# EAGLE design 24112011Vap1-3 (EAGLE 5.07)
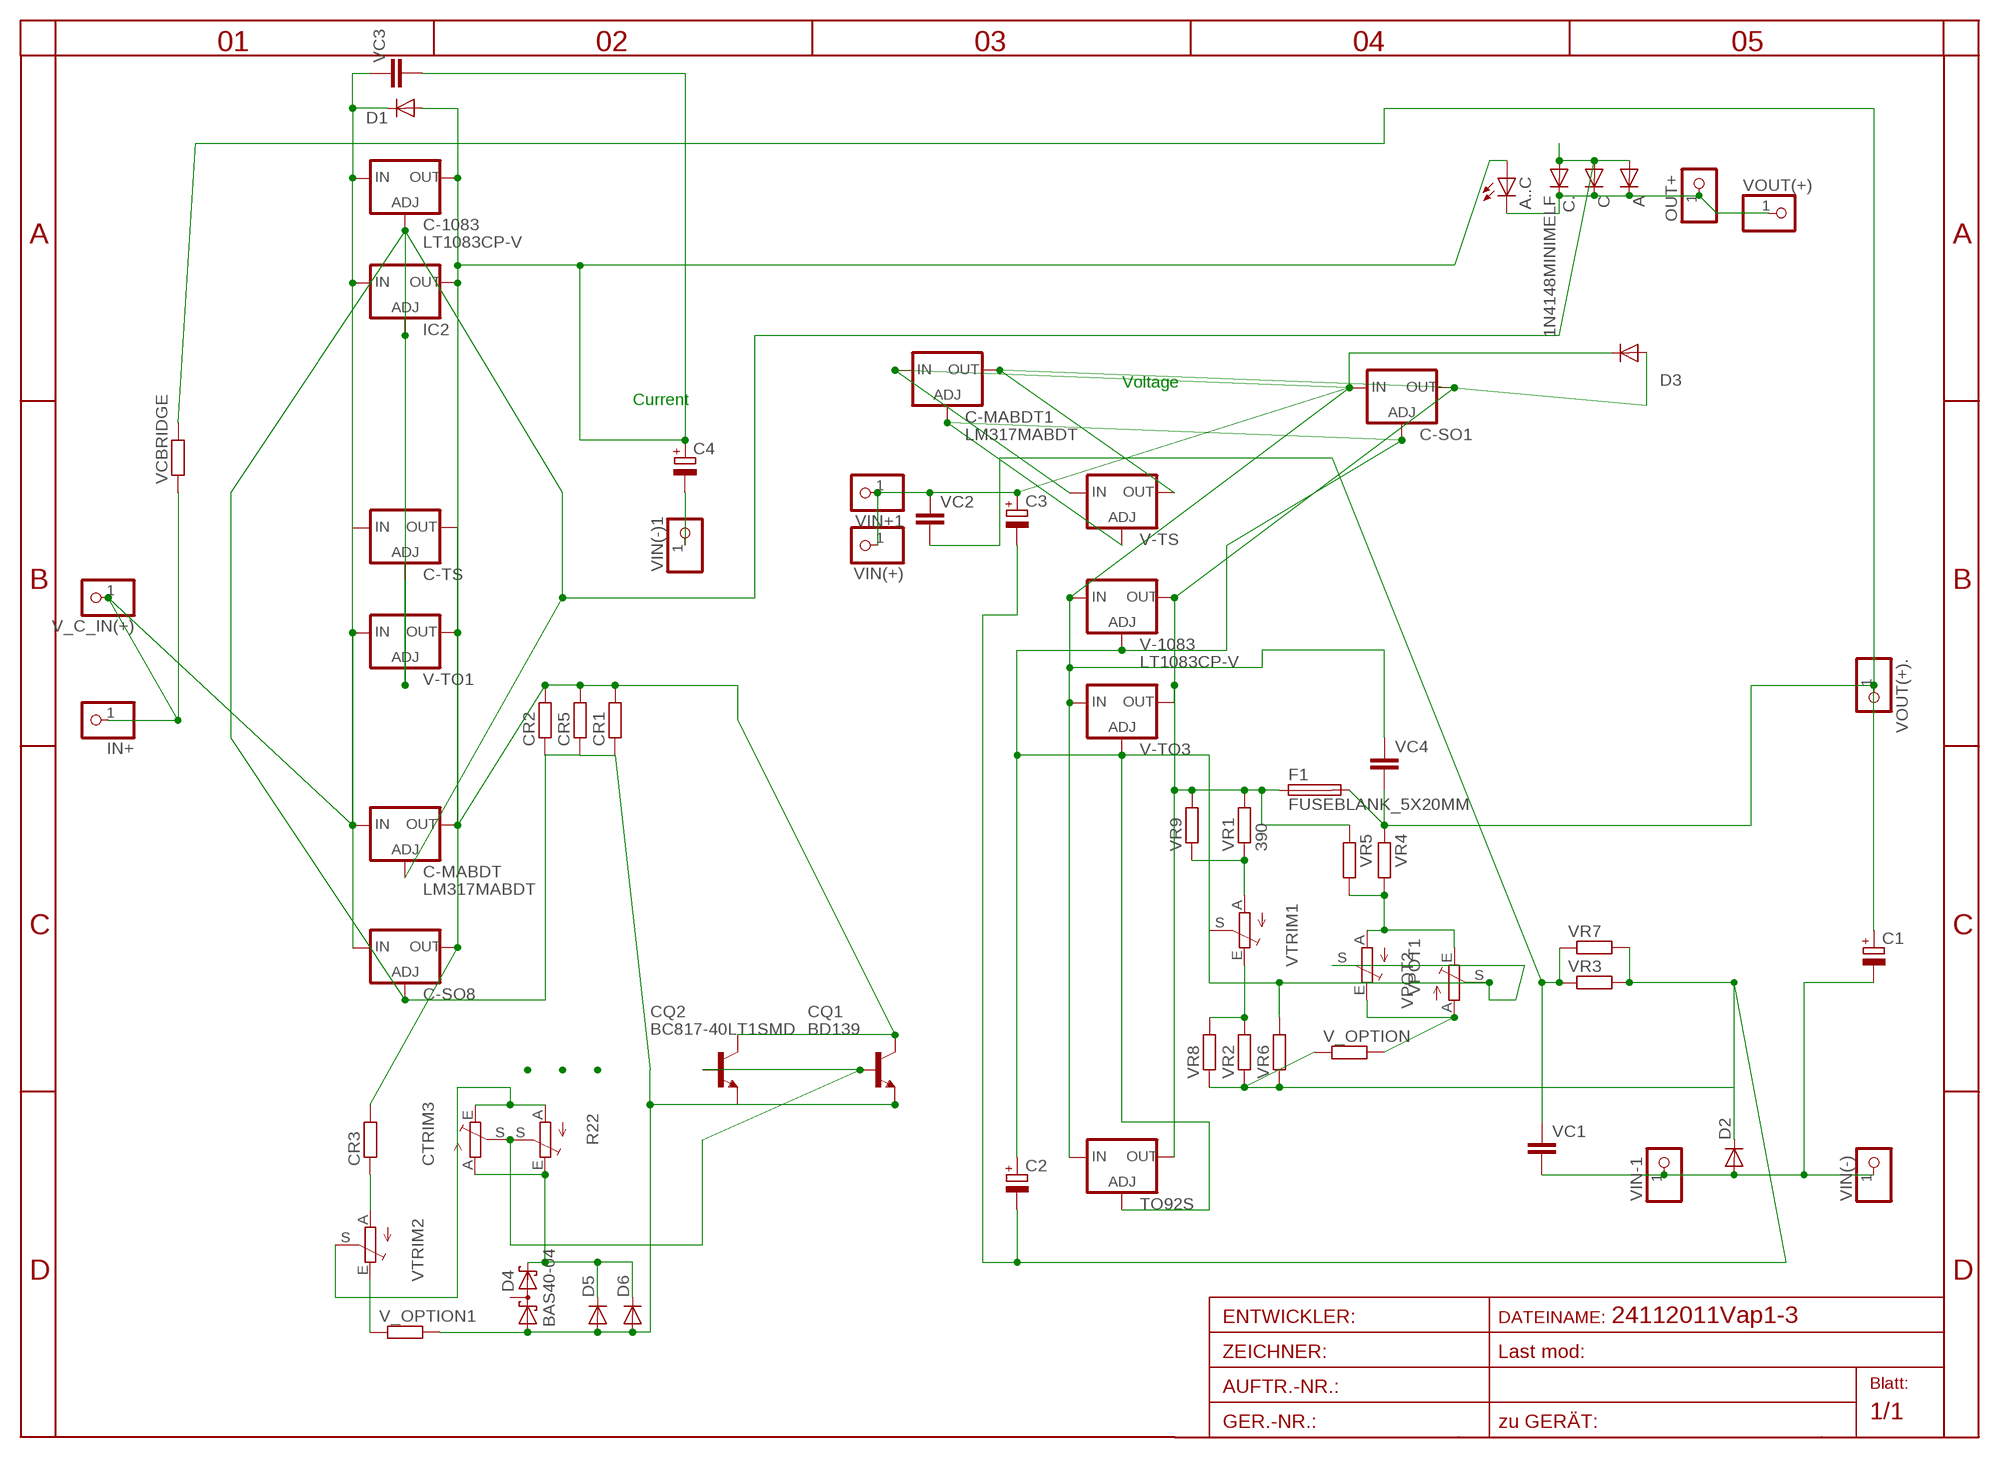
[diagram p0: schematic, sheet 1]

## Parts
A  DIODE-TO220V  [TO220ACS]
A..C  LED3MM  [LED3MM]
C  DIODE-SMC  [SMC]
C1  CPOL-EUE5-8.5  [E5-8,5]
C2  CPOL-EUE2.5-6  [E2,5-6]
C3  CPOL-EUE2.5-6  [E2,5-6]
C4  CPOL-EUE5-6  [E5-6]
C-1083  LT1083CP-V  [TO247S]
C-MABDT  LM317MABDT  [DPACK]
C-MABDT1  LM317MABDT  [DPACK]
C-SO1  LM317LM-OUTPIN7  [SO08]
C-SO8  LM317LM-OUTPIN7  [SO08]
C-TS  LM317TS  [317TS]
C.  1N4148MINIMELF  [MINIMELF]
CQ1  BD139  [TO126V]
CQ2  BC817-40LT1SMD  [SOT23-BEC]
CR1  R-EU_R5025  [R5025]
CR2  R-EU_R1206  [R1206]
CR3  R-EU_0204/5  [0204/5]
CR5  R-EU_R1210  [R1210]
CTRIM3  TRIM_EU-EVND_H  [EVND8AA]
D1  DIODE-MINIMELF  [MINIMELF]
D2  DIODE-MINIMELF  [MINIMELF]
D3  DIODE-MINIMELF  [MINIMELF]
D4  BAS40-04  [SOT23]
D5  DIODE-MINIMELF  [MINIMELF]
D6  DIODE-D-2.5  [D-2.5]
F1  FUSEBLANK_5X20MM  [FUSE_HOLDER_5X20MM]
IC2  LM317LZS  [TO92S]
IN+  PINHD-1X1  [1X01]
OUT+  PINHD-1X1  [1X01]
R22  TRIM_EU-RAND160  [RANDL]
TO92S  LM317LZS  [TO92S]
V-1083  LT1083CP-V  [TO247S]
V-TO1  LM317-TO3  [TO3-K02]
V-TO3  LM317-TO3  [TO3-K02]
V-TS  LM317TS  [317TS]
V_C_IN(+)  PINHD-1X11MM6  [1X1MM8]
V_OPTION  R-EU_0204/2V  [0204V]
V_OPTION1  R-EU_0204/2V  [0204V]
VC1  C-EU050-025X075  [C050-025X075]
VC2  C-EU050-025X075  [C050-025X075]
VC3  C-EU050-025X075  [C050-025X075]
VC4  C-EUC1206  [C1206]
VCBRIDGE  R-EU_R0402  [R0402]
VIN(+)  PINHD-1X11MM6  [1X1MM8]
VIN(-)  PINHD-1X1  [1X01]
VIN(-)1  PINHD-1X1  [1X01]
VIN+1  PINHD-1X1  [1X01]
VIN-1  PINHD-1X11MM6  [1X1MM8]
VOUT(+)  PINHD-1X11MM6  [1X1MM8]
VOUT(+).  PINHD-1X11MM6  [1X1MM8]
VPOT1  TRIM_EU-RAND160  [RANDL]
VPOT2  TRIM_EU-S64W  [S64W]
VR1  390  R-EU_0207/15  [0207/15]
VR2  R-EU_0204/2V  [0204V]
VR3  R-EU_0204/5  [0204/5]
VR4  R-EU_R1206  [R1206]
VR5  R-EU_R1206  [R1206]
VR6  R-EU_R1206  [R1206]
VR7  R-EU_R1206  [R1206]
VR8  R-EU_R1206  [R1206]
VR9  R-EU_R1206  [R1206]
VTRIM1  TRIM_EU-EVND_H  [EVND8AA]
VTRIM2  TRIM_EU-EVND_H  [EVND8AA]

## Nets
ADJ2: C2.+ C-MABDT1.1(ADJ) C-SO1.4(ADJ) TO92S.1(ADJ) V-1083.1(ADJ) V-TO3.2(ADJ) V-TS.1(ADJ) VPOT1.S VPOT2.S VR6.2
ADJUST: A.A C-1083.1(ADJ) C-MABDT.1(ADJ) C-SO8.4(ADJ) C-TS.1(ADJ) C..A C.A CQ1.3(E) CQ2.E CR1.1 CR2.1 CR5.1 D4.1(A1) D5.A D6.A IC2.1(ADJ) V-TO1.2(ADJ) V_OPTION1.2
B1: CQ1.1(B) CQ2.B CTRIM3.S R22.S
IN+1: C3.+ C-MABDT1.3(IN) C-SO1.1(IN) D3.C TO92S.3(IN) V-1083.3(IN) V-TO3.1(IN) V-TS.3(IN) VC2.1 VC4.1 VIN(+).1 VIN+1.1
IN-: C1.- D2.A VC1.2 VIN(-).1 VIN-1.1
INPUT+: C-1083.3(IN) C-MABDT.3(IN) C-SO8.1(IN) C-TS.3(IN) D1.C IC2.3(IN) IN+.1 V-TO1.1(IN) V_C_IN(+).1 VC3.1 VCBRIDGE.1
MINUS: CTRIM3.A D4.2(C2) D5.C D6.C R22.E
N$1: V_OPTION.2 VPOT1.E VPOT2.A
N$2: VPOT1.A VPOT2.E VR4.2 VR5.2
N$3: VR2.2 VR8.2 VTRIM1.E
N$4: VR1.1 VR9.1 VTRIM1.A
N$5: CTRIM3.E R22.A VTRIM2.S
N$6: CR3.1 VTRIM2.A
N$7: VC1.1 VC2.2 VR3.1 VR7.1
N$9: C4.- VIN(-)1.1
N$11: V_OPTION1.1 VTRIM2.E
OUT1: A..C.A C4.+ C-1083.2(OUT) C-MABDT.4(OUT) C-SO8.7(OUT) C-TS.2(OUT) CQ1.2(C) CQ2.C CR1.2 CR2.2 CR3.2 CR5.2 D1.A IC2.2(OUT) V-TO1.3(OUT) VC3.2
OUT2: C-MABDT1.4(OUT) C-SO1.7(OUT) D3.A F1.1 TO92S.2(OUT) V-1083.2(OUT) V-TO3.3(OUT) V-TS.2(OUT) VR1.2 VR5.1 VR9.2
OUT+: A..C.K(C) A.C C..C C.C OUT+.1 VOUT(+).1
VIRT-: C2.- C3.- D2.C V_OPTION.1 VR2.1 VR3.2 VR6.1 VR7.2 VR8.1
VOUT+: C1.+ F1.2 VC4.2 VCBRIDGE.2 VOUT(+)..1 VR4.1
Unconnected: D4.3(C1A2) VTRIM1.S

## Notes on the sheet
- Voltage
- Current

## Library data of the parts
A C D1-D3 D5 D6 = diode:DIODE-: DIODE
A..C = led:LED: LED
C1-C4 = rcl:CPOL-EU: POLARIZED CAPACITOR, European symbol
C-1083 V-1083 = linear-technology-2:LT1083*: 7.5A Low Dropout Positive Adjustable Regulators
C-MABDT C-MABDT1 = v-reg:LM317?*: 500 mA Adjustable Output Positive Voltage Regulator Source: http://www.onsemi.co.jp .. LM317M-D.PDF
C-SO1 C-SO8 IC2 TO92S = v-reg-3:LM317L: Adjustable Voltage Regulator, 1.2V to 37V, 100mA
C-TS V-TS = v-reg:LM317TS: VOLTAGE REGULATOR
C. = diode-1:1N4148: DIODE
CQ1 = transistor-npn:BD139*: NPN Transistor
CQ2 = transistor-npn:BC817*: NPN Transistor
CR1-CR3 CR5 V_OPTION V_OPTION1 VCBRIDGE VR1-VR9 = rcl-2:R-EU_: RESISTOR, European symbol
CTRIM3 R22 VPOT1 VPOT2 VTRIM1 VTRIM2 = pot:TRIM_EU-: POTENTIOMETER
D4 = diode:BAS40-04: Silicon Schottky Diodes General-purpose diode for high-speed switching
F1 = fuse:FUSE: Fuse
IN+ OUT+ VIN(-) VIN(-)1 VIN+1 = pinhead(2):PINHD-1X1: PIN HEADER
V-TO1 V-TO3 = v-reg:LM317-TO3: VOLTAGE REGULATOR
V_C_IN(+) VIN(+) VIN-1 VOUT(+) VOUT(+). = pinhead:PINHD-1X1: PIN HEADER
VC1-VC4 = rcl:C-EU: CAPACITOR, European symbol

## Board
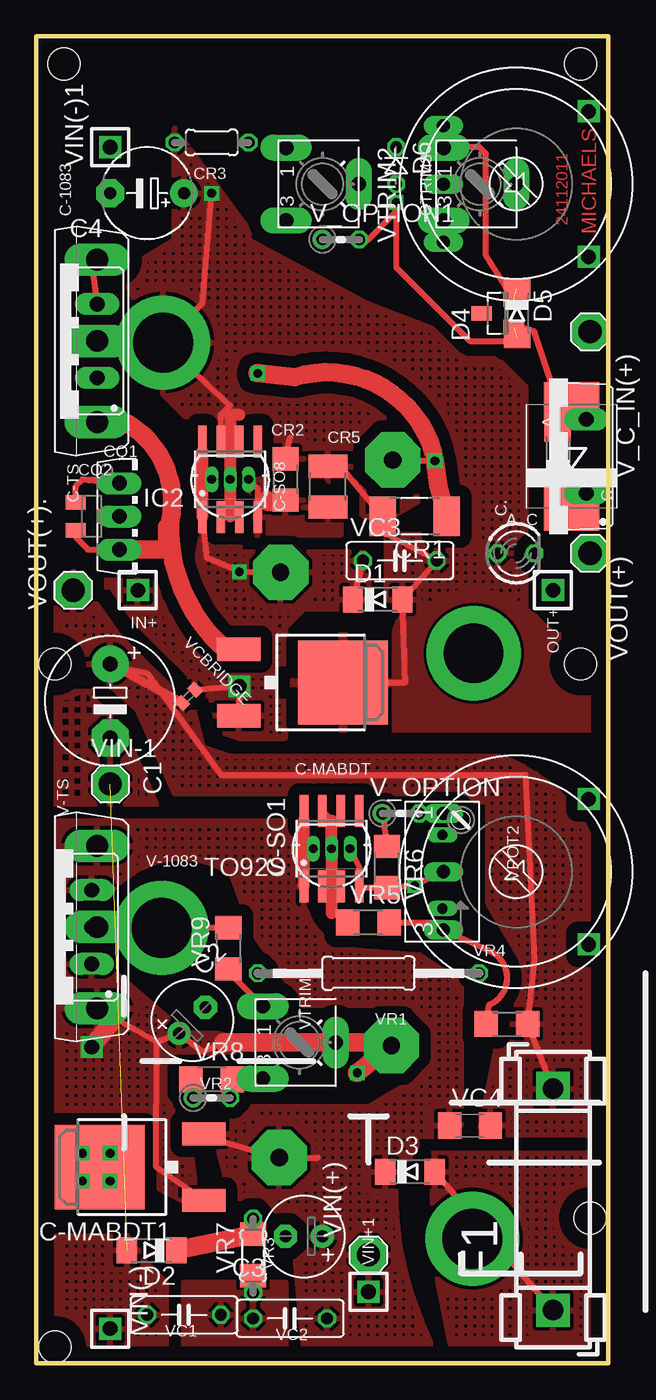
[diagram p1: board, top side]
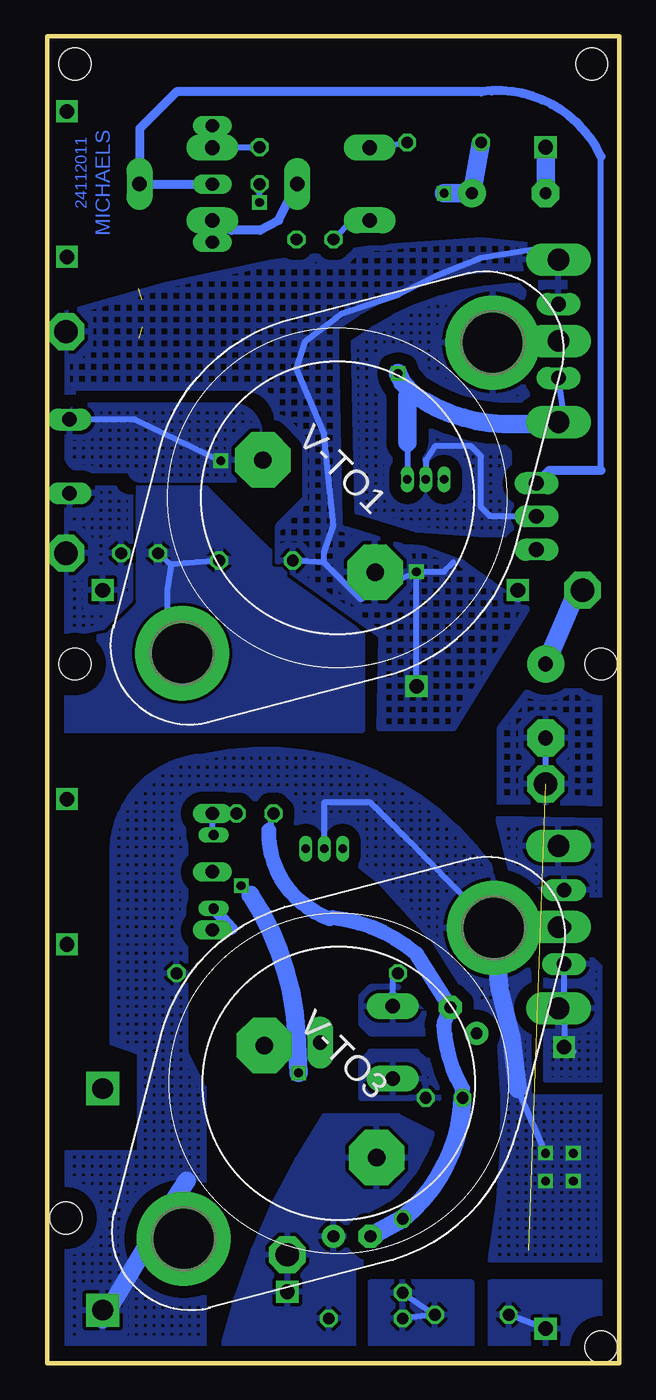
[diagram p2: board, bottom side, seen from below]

Size 39.37 x 91.27 mm. Coordinates in mm from the lower left corner, seen from the top.
Outline: 39.37,0 39.37,91.27 0,91.27 0,0 39.37,0
Copper layers (1*16): Top 0.035mm / dielectric 1.5mm / Bottom 0.035mm
Design rules "default *": minimum track width 10mil, minimum drill 24mil, track to track 8mil, track to pad 8mil, pad to pad 8mil, via to via 8mil, smd to smd 8mil, copper to edge 40mil, drill to drill 8mil, minimum pad ring 1mil, minimum via ring 8mil, stop-mask expansion 4mil, vias tented up to drill 0mil, thermal gap 10mil
Holes 2.2 mm at 37.47,89.37 1.27,48.09 37.47,48.09 1.91,89.37 38.1,10 1.27,1.1

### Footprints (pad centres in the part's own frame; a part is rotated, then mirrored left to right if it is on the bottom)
TO220ACS = drill 1.016 long: A 2.54,-2.54; C -2.54,-2.54
LED3MM = drill 0.813 octagon: A -1.27,0; K 1.27,0
SMC = smd 2.8 x 3.8: A 3.7,0; C -3.7,0
E5-8,5 = drill 1.016 pad 2.54 round: + -2.54,0 | drill 1.016 pad 2.54 octagon: - 2.54,0
E2,5-6 = drill 0.813 pad 1.6 round: + -1.27,0 | drill 0.813 pad 1.6 octagon: - 1.27,0
E5-6 = drill 0.813 pad 1.905 round: + -2.54,0 | drill 0.813 pad 1.905 octagon: - 2.54,0
TO247S = drill 1.499 long: 1 -5.588,-2.921; 2 0,-2.921; 3 5.588,-2.921
DPACK = smd 1.6 x 3: 1 -2.28,-4.8; 3 2.28,-4.8 | smd 5.8 x 6.2: 4 0,2.38
SO08 = smd 0.6 x 2.2: 1 -1.905,-2.6; 2 -0.635,-2.6; 3 0.635,-2.6; 4 1.905,-2.6; 5 1.905,2.6; 6 0.635,2.6; 7 -0.635,2.6; 8 -1.905,2.6
317TS = drill 1.016 long: 1 -2.54,-2.54; 2 0,-2.54; 3 2.54,-2.54
MINIMELF = smd 1.4 x 1.8: A 1.7,0; C -1.7,0
TO126V = drill 1.016 long: 1 -2.286,-1.27; 2 0,-1.27; 3 2.286,-1.27
SOT23-BEC = smd 1 x 1.4: B -0.95,-1.1; C 0,1.1; E 0.95,-1.1
R5025 = smd 1.8 x 2.7: 1 -2.2,0; 2 2.2,0
R1206 = smd 1.6 x 1.803: 1 -1.422,0; 2 1.422,0
0204/5 = drill 0.813 octagon: 1 -2.54,0; 2 2.54,0
R1210 = smd 1.6 x 2.7: 1 -1.4,0; 2 1.4,0
EVND8AA = drill 1 pad 1.778 long: A -2.5,-2.5; E 2.5,-2.5; S 0,2.5
SOT23 = smd 1 x 1.4: 1 -0.95,-1.1; 2 0.95,-1.1; 3 0,1.1
D-2.5 = drill 0.813 octagon: A 1.27,0; C -1.27,0
FUSE_HOLDER_5X20MM = drill 1.422 pad 2.286 square: 1 0,0; 2 15.24,0
TO92S = drill 0.6 pad 0.813 long: 1 -1.27,0; 2 0,0; 3 1.27,0
1X01 = drill 1.016 square: 1 0,0
RANDL = drill 0.9 long: A -4,5; E 4,5; S 0,5 | drill 1 square: P$1 -5,-5; P$2 5,-5
TO3-K02 = drill 1.194 pad 3.81 octagon: 1 -1.778,-5.461; 2 -1.778,5.461 | drill 4.115 pad 6.477 round: 3 15.113,0; 3@ -15.113,0
1X1MM8 = drill 1.6 pad 2.54 octagon: 1 0,0
0204V = drill 0.813 octagon: 1 -1.27,0; 2 1.27,0
C050-025X075 = drill 0.813 octagon: 1 -2.54,0; 2 2.54,0
C1206 = smd 1.6 x 1.8: 1 -1.4,0; 2 1.4,0
R0402 = smd 0.7 x 0.9: 1 -0.65,0; 2 0.65,0
S64W = drill 0.7 long: A 2.54,1.27; E -2.54,1.27; S 0,1.27
0207/15 = drill 0.813 octagon: 1 -7.62,0; 2 7.62,0

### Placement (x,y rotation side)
A  35.31,62.38 90 top
A..C  33.02,55.72 0 top
C  36.83,62.38 90 top
C1  5.08,45.55 270 top
C2  10.73,23.58 45 top
C3  18.41,8.73 180 top
C4  7.62,80.48 180 top
C-1083  1.27,70.32 90 top
C-MABDT  18.73,46.83 270 top
C-MABDT1  6.73,13.49 90 top
C-SO1  20.32,35.4 0 top
C-SO8  13.34,60.8 0 top
C-TS  1.65,70.32 90 top
C.  35.88,62.38 90 top
CQ1  6.99,58.26 270 top
CQ2  3.81,58.26 270 top
CR1  26.04,58.26 180 top
CR2  17.14,60.8 90 top
CR3  12.06,83.97 180 top
CR5  20.07,60.29 90 top
CTRIM3  30.53,81.11 270 top
D1  23.5,52.54 0 top
D2  7.94,7.77 180 top
D3  25.72,13.17 0 top
D4  31.75,72.22 90 top
D5  33.08,72.22 270 top
D6  24.77,82.38 270 top
F1  35.56,3.65 90 top
IC2  13.34,60.8 180 top
IN+  6.99,53.18 90 top
OUT+  35.56,53.18 180 top
R22  33.02,81.11 90 top
TO92S  20.32,35.4 180 top
V-1083  1.27,30 90 top
V-TO1  19.41,59.52 45 bottom
V-TO3  19.32,19.25 45 bottom
V-TS  1.27,30 90 top
V_C_IN(+)  38.1,70.95 90 top
V_OPTION  25.08,37.81 0 top
V_OPTION1  20.95,77.3 0 top
VC1  10.16,3.33 180 top
VC2  17.46,3.07 180 top
VC3  25.02,55.21 0 top
VC4  29.84,16.35 0 top
VCBRIDGE  10.48,45.87 225 top
VIN(+)  22.86,7.46 90 top
VIN(-)  5.08,2.38 90 top
VIN(-)1  5.08,83.65 90 top
VIN+1  22.86,4.92 90 top
VIN-1  5.08,39.84 0 top
VOUT(+)  38.1,55.72 90 top
VOUT(+).  2.54,53.18 90 top
VPOT1  33.02,33.81 90 top
VPOT2  29.21,33.81 90 top
VR1  22.86,26.82 0 top
VR2  12.06,18.25 0 top
VR3  14.92,7.39 90 top
VR4  32.38,23.33 180 top
VR5  22.86,30.32 0 top
VR6  24.13,34.12 270 top
VR7  14.92,7.46 90 top
VR8  12.06,19.52 0 top
VR9  13.21,28.54 90 top
VTRIM1  18.1,22.06 270 top
VTRIM2  19.68,81.11 270 top

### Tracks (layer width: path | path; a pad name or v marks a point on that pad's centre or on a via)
ADJ2  (via drill 0.6, 1)
  Top 0.406: TO92S.1 22.23,34.12 C-SO1.4 22.23,32.7 VR6.2 v26.04,32.86 VPOT2.S VPOT1.S | 12.9,22.06 11.43,21.43 C2.+ 8.28,22.12 | 8.28,22.12 V-1083.1 | C-MABDT1.1 8.26,13.49 8.28,22.12 | 24.77,22.06 V-TO3.2
  Top 1.27: v3.81,21.74 5.08,23.33 | 12.9,22.06 24.77,22.06 | V-TO3.2 v22.08,19.96
  Bottom 0.406: 4.54,24.06 V-1083.1 3.81,24.79 V-TS.1 | 4.54,24.06 5.08,23.52 | 4.54,24.06 3.81,23.33 v3.81,21.74 3.17,21.43 | 25.4,32.22 v26.04,32.86
  Bottom 1.27: 25.4,32.22 arc30 22.23,22.7 v22.08,19.96
  pour Bottom (isolate 0.813, hatched): 5.08,19.52 1.27,19.52 1.27,27.14 2.54,28.41 5.08,28.41
  pour Top (isolate 0.813, hatched): 1.27,15.71 1.27,27.14 2.54,28.41 3.81,28.41 5.08,27.14 9.53,23.33 15.24,22.06 10.16,20.16 10.16,18.25 11.11,10.63
ADJUST  (via drill 0.6)  (1 unrouted)
  Top 0.406: CQ2.E 2.71,56.81 3.56,55.97 CQ1.3 | 16.92,59.15 CR2.1 | V-TO1.2 25.23,62.06 v27.43,62.06 27.3,62.7 | 15.24,59.52 C-SO8.4 | 15.24,59.52 15.24,60.16 IC2.1 | 35.47,65.31 35.47,64.67 C.A | D4.1 33.34,71.27 34.29,70.95 35.56,67.14 C.A | A.A C..A C.A | 15.24,59.52 15.88,59.52 | D5.A 32.88,70.32 29.84,70.32 24.77,75.4 24.77,79.21 | 24.77,79.21 v24.77,79.84 | V_OPTION1.2 22.86,77.3 24.77,79.21
  Top 1.016: 8.51,55.97 8.89,56.35 8.89,57.56 9.21,57.87 | 16.92,59.15 15.88,59.15 15.88,59.52
  Top 1.27: v15.24,68.1 17.78,67.84 arc-90 27.3,62.7 | CR1.1 27.69,60.35 v27.43,62.06 | C-MABDT.1 13.6,49.11 12.7,49.37 arc-49 9.21,57.87 arc71 6.35,64.6 4.95,64.6 C-1083.1 | CQ1.3 8.51,55.97
  Bottom 0.406: C-TS.1 3.81,65.11 C-1083.1 4.95,63.97 | A.A 33.34,64.92 v27.43,62.06 | 14.61,63.34 IC2.1 | v24.77,79.84 D6.A
  Bottom 1.27: 14.61,63.34 14.61,66.51 14.16,66.64 | v15.24,68.1 14.92,67.46 14.16,66.64 | 14.16,66.64 arc-37 6.99,64.6 5.08,64.6 C-1083.1
  pour Bottom (isolate 0.813, hatched): 24.77,63.97 arc-90 26.67,65.88 36.83,65.88 arc-90 38.1,64.6 38.1,62.7 arc-90 36.83,61.43 33.66,61.43 arc-90 33.02,60.8 24.77,60.8
  pour Top (isolate 0.61): 14.61,56.98 20.95,56.98 20.95,58.89 15.88,60.16 15.88,60.8 14.61,60.8
B1
  Top 0.406: CQ2.B 2.71,60.33 3.17,60.8 | 3.17,60.8 5.46,60.8 CQ1.1 3.17,60.8
  Bottom 0.406: 1.27,61.43 1.27,83.02
  Bottom 0.61: 1.27,83.02 arc-73 9.53,87.46 30.48,87.46 33.02,84.92 CTRIM3.S R22.S | 1.27,61.43 4.83,61.43 CQ1.1
IN+1
  Top 0.406: 19.35,14.14 V-TO3.1 13.34,15.08 C-MABDT1.3 | TO92S.3 18.41,34.12 18.41,32.86 C-SO1.1
  Top 0.813: 18.41,32.86 18.41,37.3
  pour Bottom (isolate 0.813, hatched): 1.27,32.22 1.27,37.3 8.38,37.43 7.11,32.35
  pour Top (isolate 0.813, rank 3, hatched): 18.41,1.1 17.78,8.09 13.65,10.63 11.75,17.62 22.86,17.62 26.04,19.52 26.04,24.6 18.41,24.6 14.92,29.62 13.46,33.62 arc90 5.08,32.22 1.27,32.22 1.27,37.3 17.14,37.3 18.41,37.94 18.41,32.22 arc90 22.23,28.41 26.35,28.09 29.21,26.19 29.21,16.35 27.3,14.44 24.77,13.81 arc32 27.3,1.1
  pour Bottom (isolate 0.813, rank 4): 15.24,16.98 20.32,16.98 arc-20 27.3,1.1 17.78,1.1 17.78,9.36 16.51,10.63 12.7,10.63 12.7,15.71
IN-  (1 unrouted)
  Bottom 0.406: VIN(-).1 VC1.2 | VIN-1.1 C1.-
  pour Bottom (isolate 0.813, rank 2): 1.27,1.1 1.27,5.55 8.89,5.55 8.89,1.1
  pour Top (isolate 0.813, hatched): 1.27,1.1 1.27,8.73 6.99,8.73 6.99,7.46 8.89,5.55 8.89,1.1
  pour Bottom (isolate 0.813, rank 3, hatched): 0.64,46.19 6.35,46.19 8.26,43.65 8.26,37.94 1.27,37.94
  pour Top (isolate 0.813, rank 4, hatched): 0.64,46.19 6.35,46.19 8.26,43.65 8.26,37.94 1.27,37.94
INPUT+  (via drill 0.6, 1)
  Top 0.406: C-SO8.1 11.75,55.4 v13.97,54.45 V-TO1.1 | C-TS.3 3.81,75.53 C-1083.3 | VC3.1 D1.C | 11.43,60.8 IC2.3 | C-SO8.1 11.43,57.62 | C-SO8.1 11.43,58.26 | C-MABDT.3 v13.97,46.57 VCBRIDGE.1
  Top 0.813: 11.43,58.26 11.43,60.8 11.43,62.7
  Bottom 0.406: 6.99,52.54 IN+.1 | C-1083.3 4.95,76.67 5.71,76.67 9.53,76.03 12.7,74.77 15.24,73.49 19.05,72.22 21.59,70.32 22.23,68.41 20.32,63.97 19.68,57.62 20.32,55.72 20.32,55.08 | v13.97,54.45 17.78,52.54 20.32,55.08 | 11.43,55.08 12.06,54.45 v13.97,54.45 | 20.32,55.08 VC3.1 | v13.97,46.57 v13.97,54.45
  pour Top (isolate 0.813, rank 2, hatched): 17.14,43.02 17.14,50.63 18.41,51.91 22.86,51.91 22.86,55.72 21.59,55.72 20.95,56.35 12.7,56.35 12.7,56.98 12.06,57.62 11.43,57.62 10.79,53.81 4.45,53.81 12.7,43.02
  pour Bottom (isolate 0.813, rank 2, hatched): 6.35,51.91 11.43,43.65 16.51,43.65 16.38,50 23.5,55.08 23.5,57.62 21.59,59.52 21.59,62.06 24.77,66.51 38.1,66.51 38.1,72.22 arc16 9.53,77.3 3.81,76.67 3.81,72.86 13.34,72.86 19.05,69.05 18.41,58.89 17.78,57.62 10.79,55.08
MINUS  (1 unrouted)
  Top 0.406: D4.2 30.92,76.23 30.95,83.19 30.48,83.65 28.07,83.65 CTRIM3.A
  Bottom 0.406: R22.E CTRIM3.A 27.99,83.65 D6.C
N$1
  Bottom 0.406: VPOT2.A 28.02,36.35 VPOT1.E 27.18,37.81 V_OPTION.2
N$2
  Top 0.406: VR5.2 28.02,30.32 VPOT1.A 31.11,28.41 arc-135 31.11,24.6 VR4.2
  Bottom 0.813: VPOT2.E 26.67,29.89 VPOT1.A
N$3
  Top 0.406: VR8.2 VTRIM1.E
  Bottom 0.813: VTRIM1.E 15.56,19.52
  pour Bottom (isolate 0.813, rank 2, hatched): 12.06,18.25 12.06,20.16 12.38,20.79 13.34,20.79 13.97,21.43 17.14,21.43 17.78,20.79 17.78,18.25
N$4
  Top 0.406: VR9.1 13.21,26.95 VTRIM1.A
  Bottom 0.406: VR1.1 15.6,26.82 15.6,25.2
  Bottom 0.813: VTRIM1.A 15.6,25.2
  pour Bottom (isolate 0.813, rank 3, hatched): 12.7,22.7 12.7,23.33 15.24,25.87 17.14,25.87 17.78,25.23 17.78,23.33 17.14,22.7
N$5
  Bottom 0.406: 26.72,77.94 CTRIM3.E R22.A
  Bottom 0.61: VTRIM2.S 23.45,78.61 24.77,77.94 26.72,77.94
N$6
  Bottom 0.406: VTRIM2.A CR3.1
N$7
  Top 0.406: VR3.1 VR7.1
  Bottom 0.406: VR3.1 VC1.1 VC2.2
  pour Bottom (isolate 0.813, rank 3): 10.16,5.55 17.14,5.55 17.14,1.1 10.16,1.1
  pour Top (isolate 0.813, rank 3): 10.16,5.55 17.14,5.55 17.14,1.1 10.16,1.1
N$9
  Bottom 1.27: C4.- VIN(-)1.1
N$11
  Bottom 0.406: VTRIM2.E 18.38,78.61 V_OPTION1.1
OUT1  (via drill 0.6)
  Top 0.406: CQ2.C CQ1.2 | v12.06,80.48 11.43,72.91 V-TO1.3 | C-1083.2 8.62,70.32 V-TO1.3 | IC2.2 13.34,62.06 12.7,62.7 C-SO8.7 12.7,65.24 13.02,65.56 | CR2.2 17.46,63.65 | 13.02,65.56 13.34,65.88 V-TO1.3 | C-MABDT.4 25.4,46.83 D1.A VC3.2 24.13,56.98 CR1.2 21.53,60.99 20.84,61.88 CR5.2 | 13.34,65.24 13.02,65.24 13.02,65.56
  Top 0.813: 13.97,65.24 13.34,65.24 13.34,58.26
  Bottom 0.406: 30.86,54.95 31.11,53.18 31.11,51.27 | 30.86,54.95 A..C.A | CQ2.C CQ1.2 8.89,58.26 9.53,58.89 9.53,62.38 10.22,63.08 12.7,63.08 13.34,62.12 IC2.2 | VC3.2 30.86,54.95
  Bottom 1.27: v12.06,80.48 C4.+ CR3.2
  pour Top: 17.78,50 24.77,50 arc-90 26.67,51.91 arc-64 34.29,51.27 35.56,50 38.1,50 38.1,43.65 17.78,43.65
  pour Bottom (isolate 0.813, hatched): 2.54,69.68 3.81,69.68 6.35,67.14 6.35,66.51 6.99,65.88 11.43,65.88 8.26,63.34 7.62,62.7 7.62,60.16 5.71,58.26 4.45,58.26 5.08,57.62 7.62,56.98 9.53,56.98 13.91,57.3 18.03,58.57 18.29,70.26 arc33 7.62,74.13 6.99,74.13
  pour Top (isolate 0.813, rank 3, hatched): 33.66,51.27 25.4,51.27 24.13,52.54 24.13,56.98 26.67,56.98 26.67,59.52 23.5,57.62 21.59,58.89 19.05,62.06 13.34,62.06 6.35,69.05 6.35,75.4 9.53,77.3 9.53,84.92 14.61,77.94 14.61,77.3 22.86,72.86 31.11,69.68 33.66,67.14
  pour Bottom (rank 3): 17.78,50 24.77,56.35 28.57,60.16 33.02,60.16 33.02,54.45 34.92,50.63 38.73,50.63 38.73,43.65 17.78,43.65
OUT2  (via drill 0.6)
  Top 0.406: 20.32,37.3 20.38,37.3 C-SO1.7 | 20.32,30.95 21.44,30.95 VR5.1 | C-MABDT1.4 v5.08,14.44 | F1.1 D3.A | VR9.2 8.66,29.96 V-TO3.3
  Top 0.813: 20.32,37.3 TO92S.2 20.32,30.95
  Bottom 0.406: 4.25,29.94 V-1083.2 V-TS.2 | v5.08,14.44 6.99,18.89 | V-TO3.3 14.61,36.03 17.14,38.57 20.32,38.57 TO92S.2 | F1.1 35.56,3.01
  Bottom 1.27: 29.78,12.54 30.99,10.69 35.56,3.01 | V-1083.2 V-TO3.3 8.26,25.81 7.43,22.44 6.99,18.89
  other vias: 3.17,14.44 3.17,12.54 5.08,12.54
  pour Bottom (isolate 0.813, rank 6, hatched): 5.71,32.22 7.62,33.49 8.89,33.49 8.89,34.12 arc-68 28.57,41.74 arc-90 34.92,34.76 34.92,22.06 33.02,21.43 33.02,14.44 38.1,14.44 38.1,1.1 28.57,1.1 28.57,18.89 29.84,21.43 29.84,39.2 19.37,35.4 16.51,33.17 13.34,29.68 11.43,26.51 8.26,22.06 arc16 8.89,7.14 0.64,7.14 0.64,18.44 5.71,18.57
  pour Top (isolate 0.254, rank 2, hatched): 27.3,14.44 38.1,14.44 38.1,1.1 28.57,1.1 27.3,7.46
OUT+
  Top 0.406: A.C C..C C.C
  pour Bottom (isolate 0.813, rank 2, hatched): 33.66,60.16 38.73,60.16 38.73,50 35.56,50.63 33.66,52.54
VIRT-
  Top 0.406: V_OPTION.1 VR6.1 | VR2.1 VR8.1 | VR7.2 VR3.2
  Top 1.27: D2.C VR7.2
  Bottom 0.406: 24.13,36.66 V_OPTION.1
  Bottom 0.813: 19.75,30.63 19.94,30.57
  Bottom 1.016: 19.94,30.57 arc72 24.13,36.66 | 19.75,30.63 arc34 13.97,28.16 C2.- 12.06,23.33 arc-29 10.79,18.89 VR2.1
  Bottom 1.27: VR2.1 arc48 VR3.2 C3.-
VOUT+
  Top 0.406: F1.2 VR4.1 34.29,27.78 33.66,40.48 12.7,40.48 7.62,47.46 4.45,48.09 C1.+
  Top 0.61: VCBRIDGE.2 C1.+
  Bottom 1.27: C1.+ 3.17,52.54 VOUT(+)..1
  pour Top (isolate 0.813, hatched): 0.64,50.63 2.54,54.45 5.71,50 10.79,44.92 11.43,42.38 13.34,41.74 31.75,41.74 arc-86 38.73,29.68 38.73,15.71 30.48,15.71 33.02,28.41 31.11,31.59 31.11,38.57 25.4,39.2 9.53,39.2 6.99,44.92

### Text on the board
Top: 24112011 | MICHAELS
Bottom: MICHAELS | 24112011
tNames: V_in(+) | V_out(+)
